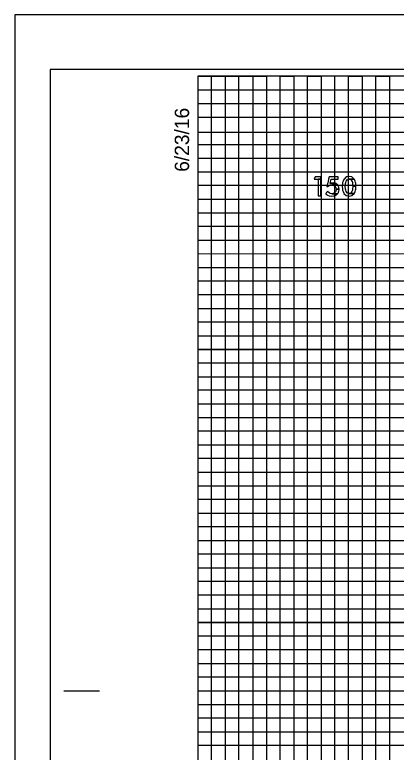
# Model space of a CAD drawing. Extents: x -13 to 323, y -5 to 1431.
# Drawn here: x -13.4 to 14.5, y 1260.5 to 1314.5 of the extents above; entities that cross this region are included whole.
import ezdxf

# ---------------------------------------------------------------- set-up
doc = ezdxf.new("R2010")
doc.units = 0
for name, color, linetype in [('Prop XS Offset Labels', 7, 'Continuous'), ('Sheet Cross Section CELL', 7, 'Continuous'), ('Sheet Cross Section Grid Major CELL', 7, 'Continuous'), ('Sheet Cross Section Grid Middle CELL', 7, 'Continuous'), ('Sheet Cross Section Grid Minor 1 CELL', 7, 'Continuous'), ('Sheet Cross Section Grid Minor 2 CELL', 7, 'Continuous'), ('Sheet Cutting Line CELL', 7, 'Continuous'), ('Sheet DOT Grid CELL', 7, 'Continuous'), ('Sheet Plot Border Inside CELL', 7, 'Continuous'), ('Sheet Plot Border Outside CELL', 7, 'Continuous')]:
    doc.layers.add(name, color=color, linetype=linetype)

msp = doc.modelspace()

# ---------------------------------------------------------------- linework, layer by layer
at = {"layer": 'Prop XS Offset Labels'}
for points in [[(8.581, 1302.641), (8.492, 1302.459), (8.99, 1302.459), (8.99, 1302.641)], [(9.427, 1301.94), (9.424, 1301.928), (9.495, 1301.928), (9.508, 1301.94), (9.524, 1301.954), (9.595, 1301.997), (9.627, 1302.007), (9.697, 1302.029), (9.811, 1302.035), (10.219, 1302.035), (10.211, 1302.05), (10.076, 1302.145), (9.655, 1302.145), (9.658, 1302.158), (9.658, 1302.158), (9.663, 1302.178), (9.738, 1302.456), (10.263, 1302.456), (10.263, 1302.641), (9.6, 1302.641), (9.554, 1302.456), (9.486, 1302.178), (9.481, 1302.158), (9.478, 1302.145), (9.454, 1302.05), (9.451, 1302.035), (9.449, 1302.029), (9.444, 1302.007), (9.441, 1301.997), (9.431, 1301.954)], [(10.851, 1301.255), (11.051, 1301.214), (11.245, 1301.255), (11.256, 1301.257), (11.422, 1301.409), (11.047, 1301.409), (11.038, 1301.411), (11.033, 1301.413), (10.928, 1301.442), (10.841, 1301.555), (10.841, 1301.556), (10.841, 1301.556), (10.813, 1301.657), (10.813, 1301.659), (10.793, 1301.732), (10.792, 1301.736), (10.774, 1301.939), (10.774, 1301.941), (10.774, 1301.943), (10.792, 1302.145), (10.812, 1302.222), (10.813, 1302.224), (10.839, 1302.322), (10.84, 1302.325), (10.928, 1302.44), (11.041, 1302.469), (11.045, 1302.47), (11.055, 1302.473), (11.425, 1302.473), (11.262, 1302.622), (11.254, 1302.624), (11.053, 1302.668), (11.053, 1302.668), (10.845, 1302.624), (10.843, 1302.622), (10.681, 1302.473), (10.678, 1302.47), (10.678, 1302.469), (10.665, 1302.44), (10.618, 1302.325), (10.617, 1302.322), (10.577, 1302.224), (10.576, 1302.222), (10.568, 1302.145), (10.547, 1301.943), (10.547, 1301.941), (10.547, 1301.939), (10.567, 1301.736), (10.568, 1301.732), (10.575, 1301.659), (10.575, 1301.657), (10.616, 1301.556), (10.617, 1301.555), (10.663, 1301.442), (10.675, 1301.413), (10.676, 1301.411), (10.679, 1301.409), (10.848, 1301.257)], [(8.781, 1302.459), (8.781, 1301.25), (8.99, 1301.25), (8.99, 1302.459)], [(9.692, 1302.158), (9.655, 1302.145), (10.076, 1302.145), (10.058, 1302.158), (9.961, 1302.178), (9.75, 1302.178)], [(9.888, 1302.192), (9.75, 1302.178), (9.96, 1302.178), (9.888, 1302.192)], [(10.083, 1301.841), (10.105, 1301.721), (10.318, 1301.721), (10.307, 1301.841), (10.307, 1301.841), (10.303, 1301.881), (10.284, 1301.916), (10.278, 1301.928), (10.271, 1301.94), (10.263, 1301.954), (10.24, 1301.997), (10.235, 1302.007), (10.223, 1302.029), (10.219, 1302.035), (9.811, 1302.035), (9.838, 1302.029), (9.928, 1302.007), (9.943, 1301.997), (10.003, 1301.954), (10.024, 1301.94), (10.031, 1301.928), (10.038, 1301.916), (10.059, 1301.881)], [(11.058, 1301.411), (11.047, 1301.409), (11.422, 1301.409), (11.425, 1301.411), (11.426, 1301.413), (11.438, 1301.442), (11.485, 1301.555), (11.485, 1301.556), (11.527, 1301.657), (11.528, 1301.659), (11.535, 1301.732), (11.535, 1301.736), (11.555, 1301.939), (11.556, 1301.941), (11.555, 1301.943), (11.328, 1301.943), (11.328, 1301.941), (11.328, 1301.939), (11.312, 1301.736), (11.312, 1301.732), (11.292, 1301.659), (11.291, 1301.657), (11.264, 1301.556), (11.263, 1301.555), (11.175, 1301.442), (11.063, 1301.413)], [(11.312, 1302.145), (11.328, 1301.943), (11.555, 1301.943), (11.536, 1302.145), (11.528, 1302.222), (11.527, 1302.224), (11.527, 1302.224), (11.488, 1302.322), (11.488, 1302.322), (11.487, 1302.325), (11.441, 1302.44), (11.44, 1302.44), (11.429, 1302.469), (11.428, 1302.47), (11.425, 1302.473), (11.055, 1302.473), (11.065, 1302.47), (11.068, 1302.469), (11.175, 1302.44), (11.262, 1302.325), (11.265, 1302.322), (11.291, 1302.224), (11.291, 1302.222)], [(9.626, 1301.233), (9.762, 1301.214), (9.959, 1301.233), (9.968, 1301.237), (10.091, 1301.297), (10.091, 1301.297), (10.141, 1301.321), (10.185, 1301.375), (10.204, 1301.399), (9.793, 1301.399), (9.683, 1301.418), (9.682, 1301.419), (9.679, 1301.42), (9.596, 1301.466), (9.586, 1301.477), (9.58, 1301.483), (9.58, 1301.483), (9.529, 1301.535), (9.497, 1301.585), (9.497, 1301.585), (9.451, 1301.535), (9.404, 1301.483), (9.399, 1301.477), (9.39, 1301.466), (9.348, 1301.42), (9.347, 1301.419), (9.348, 1301.418), (9.363, 1301.399), (9.382, 1301.375), (9.445, 1301.321), (9.474, 1301.297), (9.598, 1301.237)], [(9.424, 1301.928), (9.482, 1301.916), (9.495, 1301.928)], [(9.9, 1301.418), (9.793, 1301.399), (10.204, 1301.399), (10.22, 1301.418), (10.221, 1301.419), (10.222, 1301.42), (10.222, 1301.42), (10.259, 1301.466), (10.268, 1301.477), (10.27, 1301.483), (10.284, 1301.535), (10.299, 1301.59), (10.322, 1301.674), (10.318, 1301.721), (10.105, 1301.721), (10.097, 1301.674), (10.082, 1301.59), (10.047, 1301.535), (10.014, 1301.483), (10.004, 1301.477), (9.987, 1301.466), (9.913, 1301.42), (9.905, 1301.419)]]:
    msp.add_lwpolyline(points, close=True, dxfattribs=at)
at = {"layer": 'Sheet Cross Section CELL'}
for p, q in [((-9.8, 1265), (-7.3, 1265)), ((-9.7, 1265), (-7.2, 1265))]:
    msp.add_line(p, q, dxfattribs=at)
msp.add_lwpolyline([(320, 1310), (0, 1310), (0, 1100), (320, 1100)], close=True, dxfattribs=at)
at = {"layer": 'Sheet Cross Section Grid Major CELL'}
for p, q in [((10, 1310), (0, 1310)), ((10, 1100), (10, 1310))]:
    msp.add_line(p, q, dxfattribs=at)
for points in [[(0, 1300), (320, 1300), (320, 1290), (0, 1290)], [(0, 1280), (320, 1280), (320, 1270), (0, 1270)]]:
    msp.add_lwpolyline(points, dxfattribs=at)
at = {"layer": 'Sheet Cross Section Grid Middle CELL'}
for points in [[(0, 1310), (5, 1310), (5, 1100)], [(0, 1305), (275, 1305)], [(0, 1285), (320, 1285), (320, 1295), (0, 1295)], [(0, 1265), (320, 1265), (320, 1275), (0, 1275)]]:
    msp.add_lwpolyline(points, dxfattribs=at)
at = {"layer": 'Sheet Cross Section Grid Minor 1 CELL'}
for p, q in [((0, 1309), (260, 1309)), ((260, 1307.98), (0, 1307.98)), ((0, 1307.98), (0, 1307)), ((0, 1307), (260, 1307)), ((260, 1305.89), (0, 1305.89)), ((0, 1305.89), (0, 1304)), ((0, 1304), (320, 1304))]:
    msp.add_line(p, q, dxfattribs=at)
for points in [[(0, 1303), (270, 1303), (320, 1303), (320, 1302), (0, 1302)], [(0, 1301), (320, 1301), (320, 1299), (0, 1299)], [(0, 1298), (320, 1298), (320, 1297), (0, 1296.98)], [(0, 1296), (320, 1296), (320, 1294), (0, 1294)], [(0, 1293), (320, 1293), (320, 1292), (0, 1292)], [(0, 1291), (320, 1291), (320, 1289), (0, 1289)], [(0, 1288), (320, 1288), (320, 1287), (0, 1287)], [(0, 1286), (320, 1286), (320, 1284), (0, 1284)], [(0, 1283), (320, 1283), (320, 1282), (0, 1282)], [(0, 1281), (320, 1281), (320, 1279), (0, 1279)], [(0, 1278), (320, 1278), (320, 1277), (0, 1277)], [(0, 1276), (320, 1276), (320, 1273.95), (320, 1273), (320, 1272), (0, 1272)], [(0, 1274), (320, 1274), (320, 1273), (0, 1273)], [(0, 1271), (320, 1271), (320, 1269), (0, 1269.03)], [(0, 1269.03), (320, 1269), (320, 1268), (0, 1268)], [(0, 1267), (320, 1267), (320, 1266), (0, 1266)], [(0, 1264), (320, 1264), (320, 1263), (0, 1263)], [(0, 1262), (320, 1262), (320, 1261), (0, 1261)]]:
    msp.add_lwpolyline(points, dxfattribs=at)
at = {"layer": 'Sheet Cross Section Grid Minor 2 CELL'}
for points in [[(0, 1100), (1, 1100), (1, 1310), (2, 1310), (2, 1100)], [(2, 1100), (3, 1100), (3, 1310), (4, 1310), (4, 1100)], [(5, 1100), (6, 1100), (6, 1310), (7, 1310), (7, 1100)], [(7, 1100), (8, 1100), (8, 1310), (9, 1310), (9, 1100)], [(10, 1100), (11, 1100), (11, 1310), (12, 1310), (12, 1100)], [(12, 1100), (13, 1100), (13, 1310), (14, 1310), (14, 1100)]]:
    msp.add_lwpolyline(points, dxfattribs=at)
at = {"layer": 'Sheet Cutting Line CELL'}
for p, q in [((323.3, 1314.5), (-13.4, 1314.5)), ((-13.4, 1314.5), (-13.4, 1095.5))]:
    msp.add_line(p, q, dxfattribs=at)
at = {"layer": 'Sheet DOT Grid CELL'}
for p, q in [((10, 1100), (10, 1310)), ((0, 1300), (320, 1300)), ((0, 1290), (320, 1290)), ((0, 1280), (320, 1280)), ((0, 1270), (320, 1270))]:
    msp.add_line(p, q, dxfattribs=at)
at = {"layer": 'Sheet Plot Border Inside CELL'}
msp.add_lwpolyline([(-10.8, 1099.5), (322.4, 1099.5), (322.4, 1310.5), (-10.8, 1310.5)], close=True, dxfattribs=at)
at = {"layer": 'Sheet Plot Border Outside CELL'}
msp.add_lwpolyline([(-13.4, 1095.5), (323.3, 1095.5), (323.3, 1314.5), (-13.4, 1314.5)], close=True, dxfattribs=at)

# ---------------------------------------------------------------- texts
at = {"layer": 'Sheet Cross Section CELL'}
msp.add_text('6/23/16', height=1.05, rotation=90, dxfattribs=at).set_placement((-0.65, 1303))

doc.saveas('drawing.dxf')
